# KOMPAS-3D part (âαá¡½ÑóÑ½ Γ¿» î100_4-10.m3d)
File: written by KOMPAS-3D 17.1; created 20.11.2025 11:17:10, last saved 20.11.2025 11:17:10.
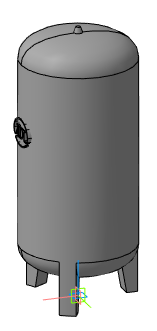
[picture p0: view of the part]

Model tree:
1. Операция без истории:4

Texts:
  REVIT MATERIAL OVERRIDDEN
  REVIT MATERIAL ID
  REVIT SUBCATEGORY ID
  REVIT CATEGORY ID
  REVIT ELEMENT ID
  REVIT BREP TAG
